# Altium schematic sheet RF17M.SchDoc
size A3; Organization: 北京必创科技有限公司; Address1: 北京市海淀区; Address2: 上地七街1号; Address3: 汇众大厦710室; Address4: Beijing，China; SheetNumber: 0; SheetTotal: 0; PageSetup: Record=PageOptions|CenterHorizontal=True|CenterVertical=True|PrintScale=0.97|XCorrection=1.00|YCorrection=1.00|PrintKind=1|BorderSize=5000000|LeftOffset=0|BottomOffset=0|Orientation=2|PaperLength=2970|PaperWidth=2100|Scale=100|PaperSource=7|PrintQuality=600|MediaType=1|DitherType=10|PaperKind=A4|PrintScaleMode=1
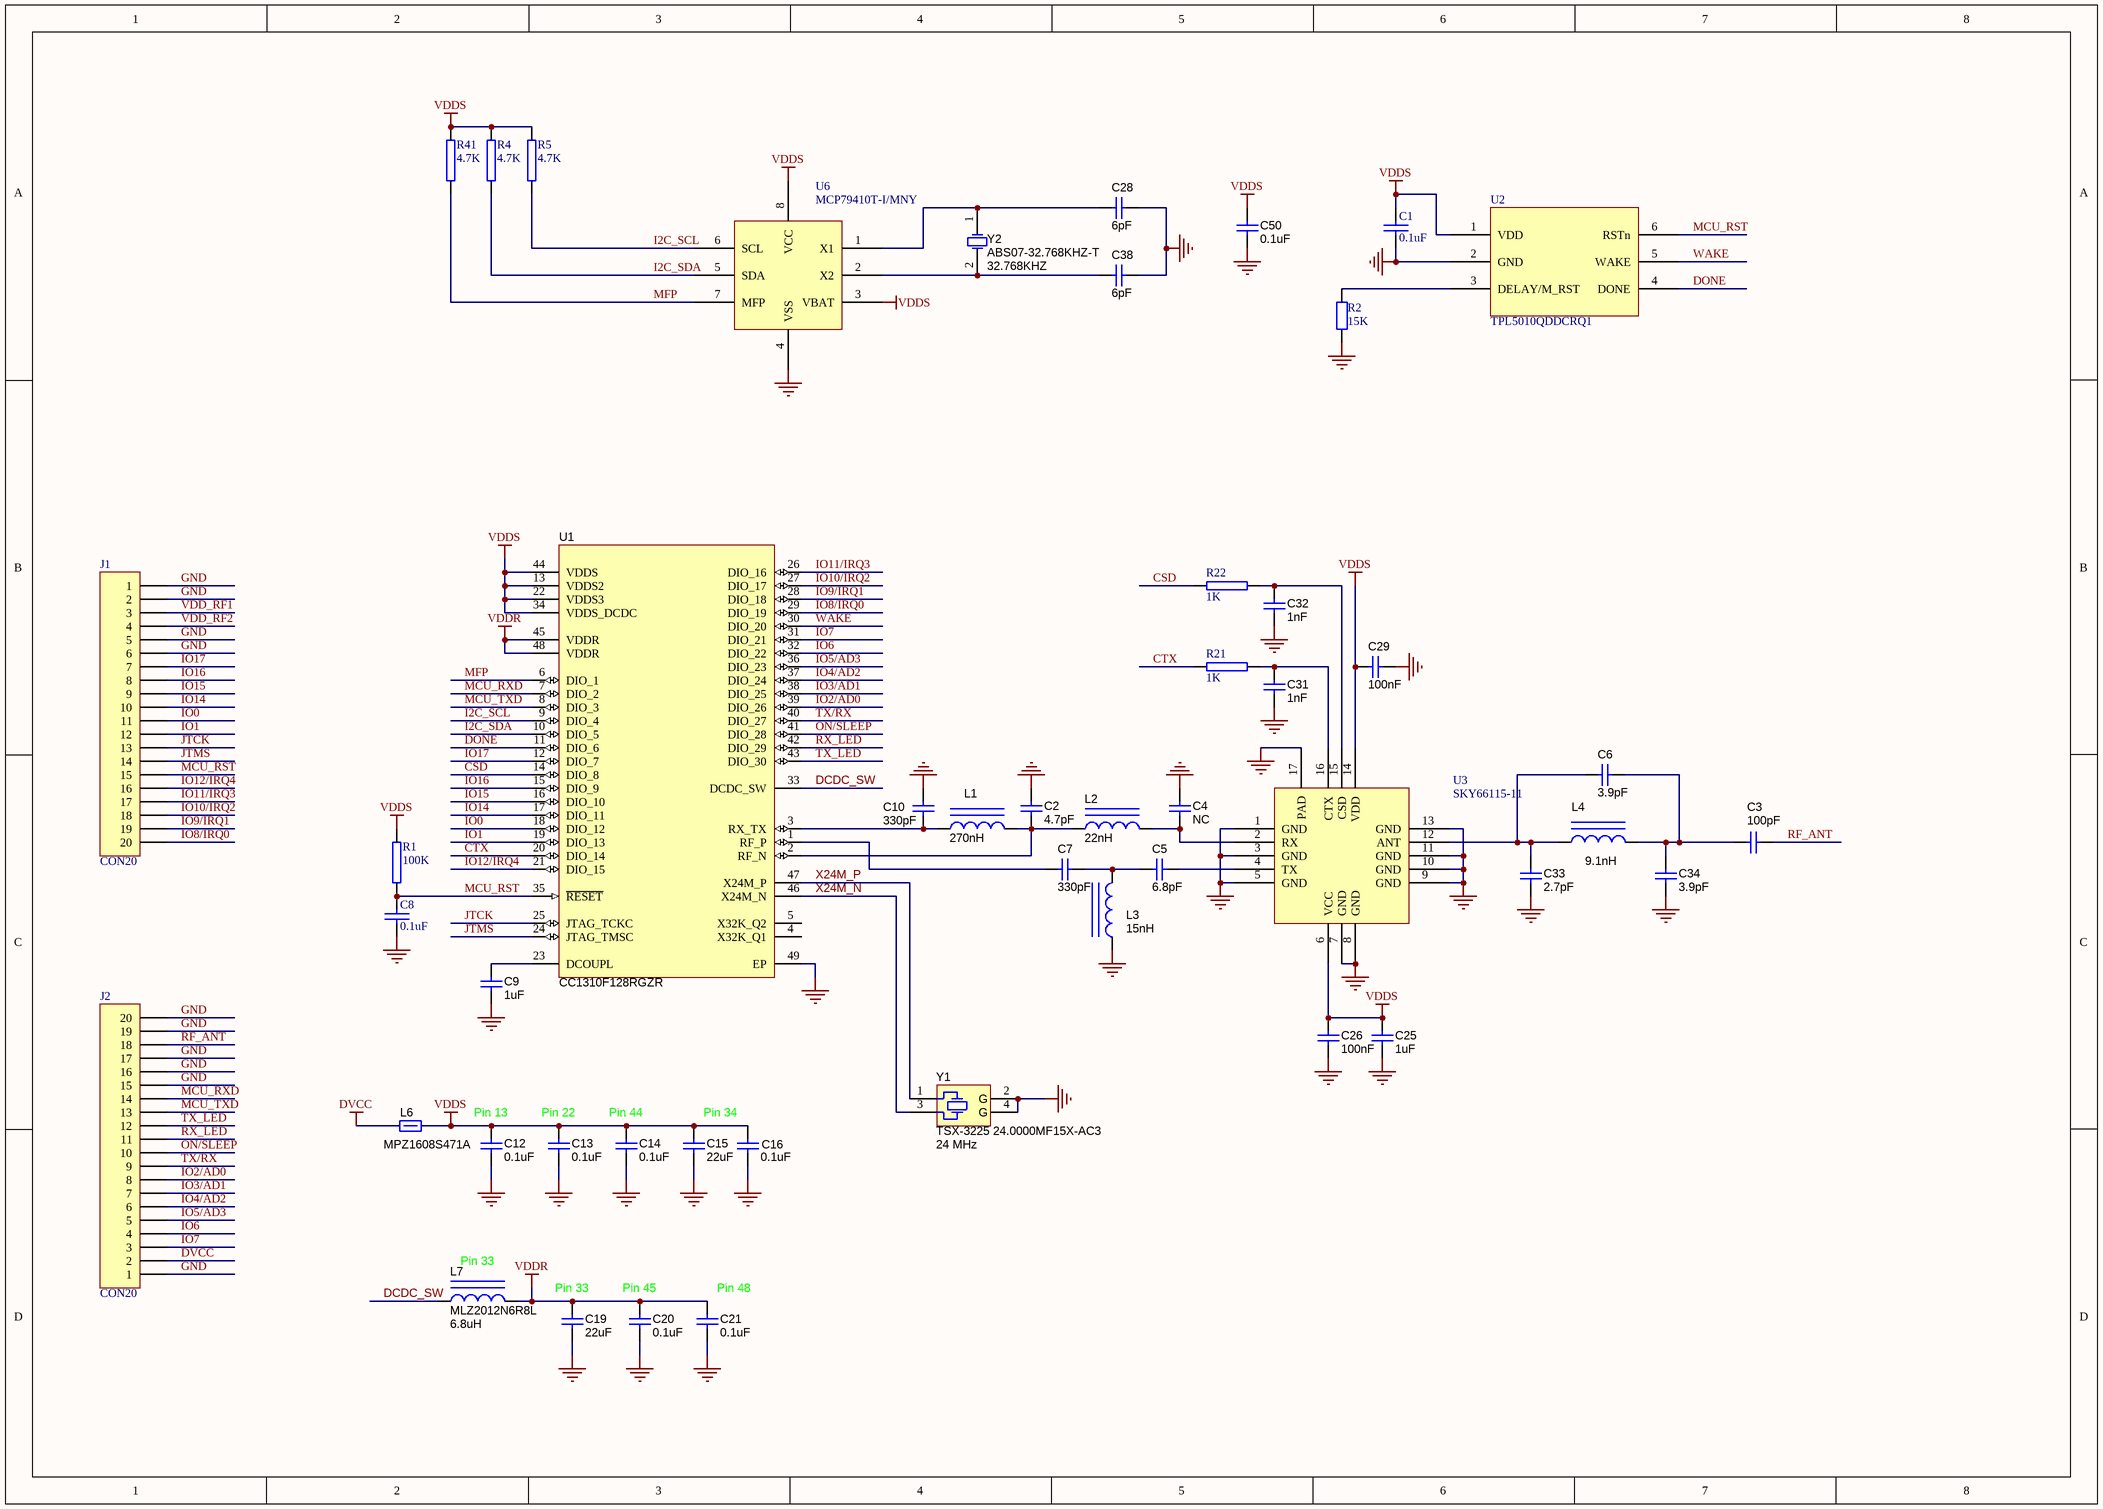
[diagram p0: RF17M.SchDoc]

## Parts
C1  0.1uF  [0402]
C2  ValueDisplayed: 4.7pF  [0402]  (hidden comment: GRM1555C1H3R6CA01D)
C3  ValueDisplayed: 100pF  [0402]  (hidden comment: GRM1555C1H330JA01D)
C4  ValueDisplayed: NC  [0402]  (hidden comment: GRM1555C1H2R2CA01D)
C5  ValueDisplayed: 6.8pF  [0402]  (hidden comment: GRM1555C1H4R7CA01D)
C6  ValueDisplayed: 3.9pF  [0402]  (hidden comment: GRM1555C1H2R2CA01D)
C7  ValueDisplayed: 330pF  [0402]  (hidden comment: GRM1555C1H3R6CA01D)
C8  0.1uF  [0402]
C9  ValueDisplayed: 1uF  [0402]  (hidden comment: GRM188R70J105KA01D)
C10  ValueDisplayed: 330pF  [0402]  (hidden comment: GRM1555C1H101JA01D)
C12  ValueDisplayed: 0.1uF  [0402]  (hidden comment: GRM155R70J104KA01D)
C13  ValueDisplayed: 0.1uF  [0402]  (hidden comment: GRM155R70J104KA01D)
C14  ValueDisplayed: 0.1uF  [0402]  (hidden comment: GRM155R70J104KA01D)
C15  ValueDisplayed: 22uF  [0603]  (hidden comment: GRM21BR70J106KE76L)
C16  ValueDisplayed: 0.1uF  [0402]  (hidden comment: GRM155R70J104KA01D)
C19  ValueDisplayed: 22uF  [0603]  (hidden comment: GRM21BR70J106KE76L)
C20  ValueDisplayed: 0.1uF  [0402]  (hidden comment: GRM155R70J104KA01D)
C21  ValueDisplayed: 0.1uF  [0402]  (hidden comment: GRM155R70J104KA01D)
C25  ValueDisplayed: 1uF  [0402]  (hidden comment: GRM1555C1H2R2CA01D)
C26  ValueDisplayed: 100nF  [0402]  (hidden comment: GRM1555C1H2R2CA01D)
C28  6pF  [0402]
C29  ValueDisplayed: 100nF  [0402]  (hidden comment: GRM1555C1H2R2CA01D)
C31  ValueDisplayed: 1nF  [0402]  (hidden comment: GRM1555C1H2R2CA01D)
C32  ValueDisplayed: 1nF  [0402]  (hidden comment: GRM1555C1H2R2CA01D)
C33  ValueDisplayed: 2.7pF  [0402]  (hidden comment: GRM1555C1H2R2CA01D)
C34  ValueDisplayed: 3.9pF  [0402]  (hidden comment: GRM1555C1H2R2CA01D)
C38  6pF  [0402]
C50  0.1uF  [0402]
J1  CON20  [SMD20_1.27MM]
J2  CON20  [SMD20_1.27MM]
L1  value 270nH  [0402]  (hidden comment: LQW15AN18NJ00D)
L2  value 22nH  [0402]  (hidden comment: LQW15AN8N2G00D)
L3  value 15nH  [0402]  (hidden comment: LQW15AN8N2G00D)
L4  value 9.1nH  [0402]  (hidden comment: LQW15AN6N8G00D)
L6  MPZ1608S471A  [0603]
L7  MLZ2012N6R8L  ValueDisplayed: 6.8uH  [0805]
R1  100K  [0402]
R2  15K  [0402]
R4  4.7K  [0402]
R5  4.7K  [0402]
R21  1K  [0402]
R22  1K  [0402]
R41  4.7K  [0402]
U1  CC1310F128RGZR  [RGZ0048]
U2  TPL5010QDDCRQ1  [SOT23-6L]
U3  SKY66115-11  [SKY66115-11]
U6  MCP79410T-I/MNY  [TDFN-8]
Y1  TSX-3225 24.0000MF15X-AC3  Frequency: 24 MHz  [TSX-3225]
Y2  ABS07-32.768KHZ-T  Frequency: 32.768KHZ  [ABS07]

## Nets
DVCC: J2.2 L6.2
GND: C1.2 C2.1 C4.1 C8.2 C9.1 C10.1 C12.2 C13.2 C14.2 C15.2 C16.2 C19.2 C20.2 C21.2 C25.1 C26.1 C28.1 C29.2 C31.2 C32.2 C33.1 C34.2 C38.1 C50.2 J1.1 J1.2 J1.5 J1.6 J2.1 J2.15 J2.16 J2.17 J2.19 J2.20 L3.1 R2.1 U1.49(EP) U2.2(GND) U3.1(GND) U3.3(GND) U3.5(GND) U3.7(GND) U3.8(GND) U3.9(GND) U3.10(GND) U3.11(GND) U3.13(GND) U3.17(PAD) U6.4(VSS) Y1.2(GND) Y1.4(GND)
VDDR: C19.1 C20.1 C21.1 L7.2 U1.45(VDDR) U1.48(VDDR)
VDDS: C1.1 C12.1 C13.1 C14.1 C15.1 C16.1 C25.2 C26.2 C29.1 C50.1 L6.1 R1.2 R4.1 R5.1 R41.1 U1.13(VDDS2) U1.22(VDDS3) U1.34(VDDS_DCDC) U1.44(VDDS) U2.1(VDD) U3.6(VCC) U3.14(VDD) U6.3(VBAT) U6.8(VCC)
CSD: R22.1 U1.14(DIO_8)
CTX: R21.1 U1.20(DIO_14)
DCDC_SW: L7.1 U1.33(DCDC_SW)
DONE: U1.11(DIO_6) U2.4(DONE)
I2C_SCL: R5.2 U1.9(DIO_4) U6.6(SCL)
I2C_SDA: R4.2 U1.10(DIO_5) U6.5(SDA)
IO0: J1.11 U1.18(DIO_12)
IO1: J1.12 U1.19(DIO_13)
IO2/AD0: J2.8 U1.39(DIO_26)
IO3/AD1: J2.7 U1.38(DIO_25)
IO4/AD2: J2.6 U1.37(DIO_24)
IO5/AD3: J2.5 U1.36(DIO_23)
IO6: J2.4 U1.32(DIO_22)
IO7: J2.3 U1.31(DIO_21)
IO8/IRQ0: J1.20 U1.29(DIO_19)
IO9/IRQ1: J1.19 U1.28(DIO_18)
IO10/IRQ2: J1.18 U1.27(DIO_17)
IO11/IRQ3: J1.17 U1.26(DIO_16)
IO12/IRQ4: J1.16 U1.21(DIO_15)
IO14: J1.10 U1.17(DIO_11)
IO15: J1.9 U1.16(DIO_10)
IO16: J1.8 U1.15(DIO_9)
IO17: J1.7 U1.12(DIO_7)
JTCK: J1.13 U1.25(JTAG_TCKC)
JTMS: J1.14 U1.24(JTAG_TMSC)
MCU_RST: C8.1 J1.15 R1.1 U1.35(~{RESET}) U2.6(RSTn)
MCU_RXD: J2.14 U1.7(DIO_2)
MCU_TXD: J2.13 U1.8(DIO_3)
MFP: R41.2 U1.6(DIO_1) U6.7(MFP)
ON/SLEEP: J2.10 U1.41(DIO_28)
RF_ANT: C3.1 J2.18
RX_LED: J2.11 U1.42(DIO_29)
TX/RX: J2.9 U1.40(DIO_27)
TX_LED: J2.12 U1.43(DIO_30)
VDD_RF1: J1.3
VDD_RF2: J1.4
WAKE: U1.30(DIO_20) U2.5(WAKE)
X24M_N: U1.46(X24M_N) Y1.3
X24M_P: U1.47(X24M_P) Y1.1
NetC2_2: C2.2 L1.2 L2.1 U1.2(RF_N)
NetC3_2: C3.2 C6.2 C34.1 L4.2
NetC4_2: C4.2 L2.2 U3.2(RX)
NetC5_1: C5.1 C7.1 L3.2
NetC5_2: C5.2 U3.4(TX)
NetC6_1: C6.1 C33.2 L4.1 U3.12(ANT)
NetC7_2: C7.2 U1.1(RF_P)
NetC9_2: C9.2 U1.23(DCOUPL)
NetC10_2: C10.2 L1.1 U1.3(RX_TX)
NetC28_2: C28.2 U6.1(X1) Y2.1(OSC1)
NetC31_1: C31.1 R21.2 U3.16(CTX)
NetC32_1: C32.1 R22.2 U3.15(CSD)
NetC38_2: C38.2 U6.2(X2) Y2.2(OSC2)
NetR2_2: R2.2 U2.3(DELAY/M_RST)

Not connected (* = marked no-connect by the designer): U1 4(X32K_Q1) 5(X32K_Q2)

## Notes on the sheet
- (near C12) Pin 13
- (near C13) Pin 22
- (near C14) Pin 44
- Pin 34
- (near L7) Pin 33
- (near C19) Pin 33
- (near C20) Pin 45
- (near C21) Pin 48

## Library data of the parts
C1 C8 = CAP: Capacitor
C2 C7 = GRM1555C1H3R6CA01D: CAP, CERM, 3.6 pF, 50 V, +/- 5%, C0G/NP0, 0402; Manufacturer: MuRata; Polarized: N; CompType: Capacitor; Value: 3.6pF; U/M: EA; Cap_F: 0.0000000000036; Tolerance_%: 5; Value1: Unknown; VDC_V: 50; Value2: 50V; TaMin_C: -55; TaMax_C: 125
C3 = GRM1555C1H330JA01D: CAP, CERM, 33 pF, 50 V, +/- 5%, C0G/NP0, 0402; Manufacturer: MuRata; Polarized: N; CompType: Capacitor; Value: 33pF; U/M: EA; Cap_F: 0.000000000033; Tolerance_%: 5; Value1: Unknown; VDC_V: 50; Value2: 50V; TaMin_C: -55; TaMax_C: 125
C4 C6 C25 C26 C29 C31-C34 = GRM1555C1H2R2CA01D: CAP, CERM, 2.2 pF, 50 V, +/- 5%, C0G/NP0, 0402; Manufacturer: MuRata; Polarized: N; CompType: Capacitor; Value: 2.2pF; U/M: EA; Cap_F: 0.0000000000022; Tolerance_%: 5; Value1: Unknown; VDC_V: 50; Value2: 50V; TaMin_C: -55; TaMax_C: 125
C5 = GRM1555C1H4R7CA01D: CAP, CERM, 4.7 pF, 50 V, +/- 5%, C0G/NP0, 0402; Manufacturer: MuRata; Polarized: N; CompType: Capacitor; Value: 4.7pF; U/M: EA; Cap_F: 0.0000000000047; Tolerance_%: 5; Value1: Unknown; VDC_V: 50; Value2: 50V; TaMin_C: -55; TaMax_C: 125
C9 = GRM188R70J105KA01D: CAP, CERM, 1 µF, 6.3 V, +/- 10%, X7R, 0603; Manufacturer: MuRata; Polarized: N; CompType: Capacitor; Value: 1uF; U/M: EA; Cap_F: 0.000001; Tolerance_%: 10; Value1: Unknown; VDC_V: 6.3; Value2: 6.3V; TaMin_C: -55; TaMax_C: 125; Cap_Case: 0603
C10 = GRM1555C1H101JA01D: CAP, CERM, 100 pF, 50 V, +/- 5%, C0G/NP0, 0402; Manufacturer: MuRata; Polarized: N; CompType: Capacitor; Value: 100pF; U/M: EA; Cap_F: 0.0000000001; Tolerance_%: 5; Value1: Unknown; VDC_V: 50; Value2: 50V; TaMin_C: -55; TaMax_C: 125
C12-C14 C16 C20 C21 = GRM155R70J104KA01D: CAP, CERM, 0.1 µF, 6.3 V, +/- 10%, X7R, 0402; Manufacturer: MuRata; Polarized: N; CompType: Capacitor; Value: 0.1uF; U/M: EA; Cap_F: 0.0000001; Tolerance_%: 10; Value1: Unknown; VDC_V: 6.3; Value2: 6.3V; TaMin_C: -55; TaMax_C: 125
C15 C19 = GRM21BR70J106KE76L: CAP, CERM, 10 µF, 6.3 V, +/- 10%, X7R, 0805; Manufacturer: MuRata; Polarized: N; CompType: Capacitor; Value: 10uF; U/M: EA; Cap_F: 0.00001; Tolerance_%: 10; Value1: Unknown; VDC_V: 6.3; Value2: 6.3V; TaMin_C: -55; TaMax_C: 125; Cap_Case: 0805
C28 C38 = 06035A120JAT2A: CAP, CERM, 12 pF, 50 V, +/- 5%, C0G/NP0, 0603; Manufacturer: AVX; Polarized: N; CompType: Capacitor; Value: 12pF; U/M: EA; Cap_F: 0.000000000012; Tolerance_%: 5; ESR_ohm: 0.363; Value1: 0.363 ohm; VDC_V: 50; Value2: 50V; TaMin_C: -55; TaMax_C: 125; Cap_Case: 0603
C50 = GRM155R70J104KA01D: CAP, CERM, 0.1 µF, 6.3 V, +/- 10%, X7R, 0402; Manufacturer: MuRata; Polarized: N; CompType: Capacitor; U/M: EA; Cap_F: 0.0000001; Tolerance_%: 10; Value1: Unknown; VDC_V: 6.3; Value2: 6.3V; TaMin_C: -55; TaMax_C: 125
J1 J2 = CON20: Connector
L1 = LQW15AN18NJ00D: Inductor, Wirewound, 18 nH, 0.37 A, 0.27 ohm, SMD; Manufacturer: MuRata; Ind_H: 18.0E-9; ValueDisplayed: 18nH; Imax_A: 0.37; DCR_ohm: 0.27; Value2: 0.37A
L2 L3 = LQW15AN8N2G00D: Inductor, Wirewound, 8.2 nH, 0.54 A, 0.14 ohm, SMD; Manufacturer: MuRata; Ind_H: 8.2E-9; ValueDisplayed: 8.2nH; Imax_A: 0.54; DCR_ohm: 0.14; Value2: 0.54A
L4 = LQW15AN6N8G00D: Inductor, Wirewound, 6.8 nH, 0.7 A, 0.09 ohm, SMD; Manufacturer: MuRata; Ind_H: 6.8E-9; ValueDisplayed: 6.8nH; Imax_A: 0.7; DCR_ohm: 0.09; Value2: 0.7A
L6 = BLM18HE152SN1D: Ferrite Bead, 1500 ohm @ 100 MHz, 0.5 A, 0603_950; Manufacturer: MuRata; Imax_A: 0.5; Value1: 0.5 ohm; Value2: 0.5A; ZTyp@100MHz_Ohm: 1500
L7 = CKS2125100M-T: Inductor, Multilayer, Ferrite, 10 µH, 0.11 A, 0.52 ohm, SMD; Manufacturer: Taiyo Yuden; Value: 10uH; Ind_H: 10.0E-6; Imax_A: 0.11; DCR_ohm: 0.52; Value2: 0.11A
R1 R4 R5 R21 R22 R41 = RES2
R2 = Res2: Resistor
U1 = CC1310F128RGZR: Sub-1 GHz and 2.4 GHz Multi-standard RF IC Family, RGZ0048A; Alternate PartNumber: CC1310F128RGZT; Manufacturer: Texas Instruments; SymbolCreator: Altium; U/M: EA
Y1 = TSX-3225 24.0000MF20G-AC3: Crystal, 24 MHz, 9 pF, SMD; Manufacturer: Epson; SymbolCreator: a0412235; U/M: EA; TaMin_C: -40; TaMax_C: 85; Frequency Stability: ?0ppm
Y2 = FC-12M 32.7680KA-A3: Crystal, 32.768kHz, 12.5pF, SMD; Manufacturer: Epson; SymbolCreator: a0412235; U/M: EA; TaMin_C: -40; TaMax_C: 85; Frequency Stability: ?0ppm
